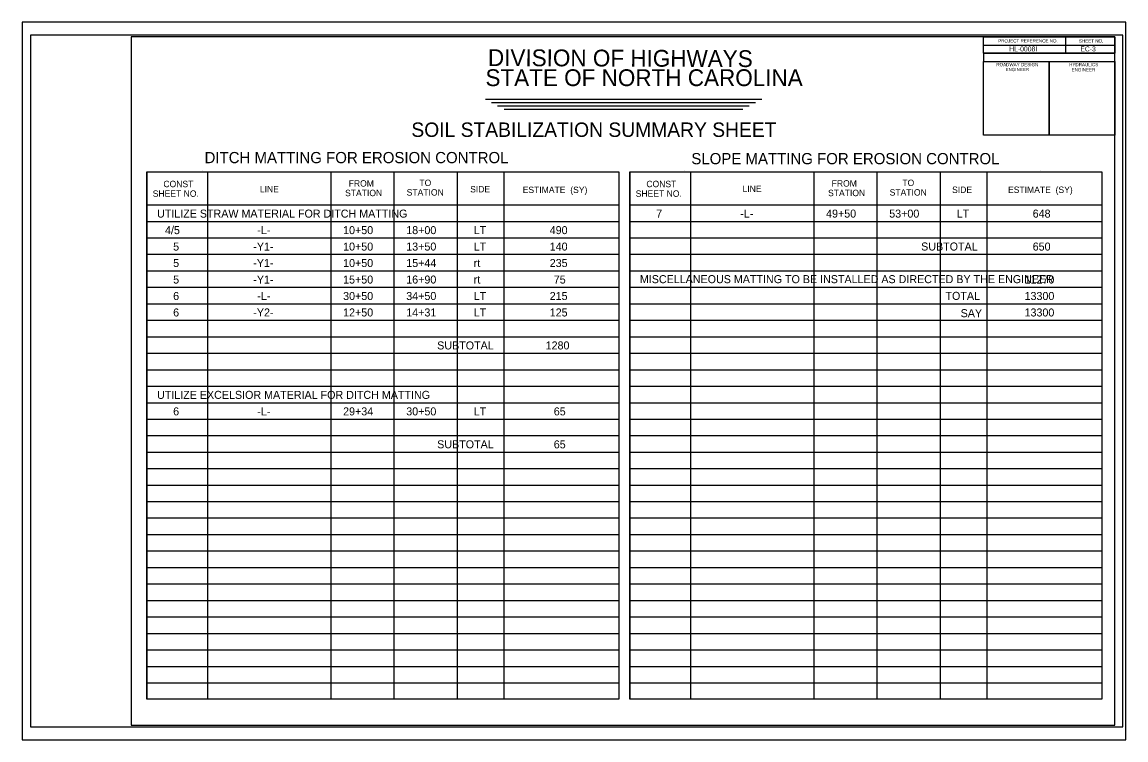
# Model space of a CAD drawing. Extents: x 1206208 to 1207892, y 737235 to 738330.
import ezdxf

# ---------------------------------------------------------------- set-up
doc = ezdxf.new("R2010")
doc.units = 0
for name, color, linetype in [('Matting and PSRM Summary Sheet CELL', 7, 'Continuous'), ('Sheet Plot Border Inside CELL', 7, 'Continuous'), ('Sheet Plot Border Outside CELL', 7, 'Continuous')]:
    doc.layers.add(name, color=color, linetype=linetype)

msp = doc.modelspace()

# ---------------------------------------------------------------- linework, layer by layer
at = {"layer": 'Matting and PSRM Summary Sheet CELL'}
for p, q in [((1207892, 738329.7), (1207892, 738329.7)), ((1206375, 738307.2), (1206375, 738307.2)), ((1207800, 738307.1), (1207800, 738282.1)), ((1207887.5, 738309.7), (1207887.5, 738309.7)), ((1207674.9, 738294.6), (1207875, 738294.6)), ((1207674.9, 738282.1), (1207674.9, 738269.6)), ((1207674.9, 738282.1), (1207875, 738282.1)), ((1207775, 738269.6), (1207775, 738157.2)), ((1206915.4, 738212.3), (1207336.6, 738212.3)), ((1206924.6, 738207.1), (1207326.9, 738207.1)), ((1206933.8, 738201.7), (1207317.3, 738201.7)), ((1206943.5, 738196.8), (1207307.7, 738196.8)), ((1206398.8, 738101), (1206398.8, 737296.6)), ((1206482.9, 738102.5), (1206482.9, 738102.5)), ((1206491.5, 738101), (1206491.5, 737296.6)), ((1206679.4, 738101), (1206679.4, 737296.6)), ((1206775.7, 738101), (1206775.7, 737296.6)), ((1206872, 738101), (1206872, 737296.6)), ((1206943.4, 738101), (1206943.4, 737296.6)), ((1207135.4, 738101), (1207135.4, 737296.6)), ((1207135.4, 738101), (1207855.1, 738101)), ((1207219.5, 738102.5), (1207219.5, 738102.5)), ((1207228.1, 738101), (1207228.1, 737296.6)), ((1207416, 738101), (1207416, 737296.6)), ((1207512.3, 738101), (1207512.3, 737296.6)), ((1207608.6, 738101), (1207608.6, 737296.6)), ((1207680.1, 738101), (1207680.1, 737296.6)), ((1207761, 738102.5), (1207761, 738102.5)), ((1206398.8, 738050.8), (1207118.4, 738050.8)), ((1207135.4, 738050.8), (1207855.1, 738050.8)), ((1206398.8, 738025.6), (1207118.4, 738025.6)), ((1207135.4, 738025.6), (1207855.1, 738025.6)), ((1206398.8, 738000.5), (1207118.4, 738000.5)), ((1207135.4, 738000.5), (1207855.1, 738000.5)), ((1206398.8, 737975.4), (1207118.4, 737975.4)), ((1207135.4, 737975.4), (1207855.1, 737975.4)), ((1206398.8, 737950.2), (1207118.4, 737950.2)), ((1207135.4, 737950.2), (1207855.1, 737950.2)), ((1206398.8, 737925.1), (1207118.4, 737925.1)), ((1207135.4, 737925.1), (1207855.1, 737925.1)), ((1206398.8, 737899.9), (1207118.4, 737899.9)), ((1207135.4, 737899.9), (1207855.1, 737899.9)), ((1206398.8, 737874.8), (1207118.4, 737874.8)), ((1207135.4, 737874.8), (1207855.1, 737874.8)), ((1206398.8, 737849.7), (1207118.4, 737849.7)), ((1207135.4, 737849.7), (1207855.1, 737849.7)), ((1206398.8, 737824.5), (1207118.4, 737824.5)), ((1207135.4, 737824.5), (1207855.1, 737824.5)), ((1206398.8, 737799.4), (1207118.4, 737799.4)), ((1207135.4, 737799.4), (1207855.1, 737799.4)), ((1206398.8, 737774.3), (1207118.4, 737774.3)), ((1207135.4, 737774.3), (1207855.1, 737774.3)), ((1206398.8, 737749.1), (1207118.4, 737749.1)), ((1207135.4, 737749.1), (1207855.1, 737749.1)), ((1206398.8, 737724), (1207118.4, 737724)), ((1207135.4, 737724), (1207855.1, 737724)), ((1206398.8, 737698.8), (1207118.4, 737698.8)), ((1207135.4, 737698.8), (1207855.1, 737698.8)), ((1206398.8, 737673.7), (1207118.4, 737673.7)), ((1207135.4, 737673.7), (1207855.1, 737673.7)), ((1206398.8, 737648.6), (1207118.4, 737648.6)), ((1207135.4, 737648.6), (1207855.1, 737648.6)), ((1206398.8, 737623.4), (1207118.4, 737623.4)), ((1207135.4, 737623.4), (1207855.1, 737623.4)), ((1206398.8, 737598.3), (1207118.4, 737598.3)), ((1207135.4, 737598.3), (1207855.1, 737598.3)), ((1206398.8, 737573.2), (1207118.4, 737573.2)), ((1207135.4, 737573.2), (1207855.1, 737573.2)), ((1206398.8, 737548), (1207118.4, 737548)), ((1207135.4, 737548), (1207855.1, 737548)), ((1206398.8, 737522.9), (1207118.4, 737522.9)), ((1207135.4, 737522.9), (1207855.1, 737522.9)), ((1206398.8, 737497.7), (1207118.4, 737497.7)), ((1207135.4, 737497.7), (1207855.1, 737497.7)), ((1206398.8, 737472.6), (1207118.4, 737472.6)), ((1207135.4, 737472.6), (1207855.1, 737472.6)), ((1206398.8, 737447.5), (1207118.4, 737447.5)), ((1207135.4, 737447.5), (1207855.1, 737447.5)), ((1206398.8, 737422.3), (1207118.4, 737422.3)), ((1207135.4, 737422.3), (1207855.1, 737422.3)), ((1206398.8, 737397.2), (1207118.4, 737397.2)), ((1207135.4, 737397.2), (1207855.1, 737397.2)), ((1206398.8, 737372.1), (1207118.4, 737372.1)), ((1207135.4, 737372.1), (1207855.1, 737372.1)), ((1206398.8, 737346.9), (1207118.4, 737346.9)), ((1207135.4, 737346.9), (1207855.1, 737346.9)), ((1206398.8, 737321.8), (1207118.4, 737321.8)), ((1207135.4, 737321.8), (1207855.1, 737321.8)), ((1206375, 737257.2), (1206375, 737257.2)), ((1206221.5, 737254.7), (1206221.5, 737254.7)), ((1206208.5, 737234.7), (1206208.5, 737234.7))]:
    msp.add_line(p, q, dxfattribs=at)
for points in [[(1207875, 738307.2), (1206375, 738307.2), (1206375, 737257.2), (1207875, 737257.2)], [(1207674.9, 738307.2), (1207875, 738307.2), (1207875, 738282.1), (1207674.9, 738282.1)], [(1207674.9, 738269.6), (1207775, 738269.6), (1207775, 738157.1), (1207674.9, 738157.1)], [(1207775, 738269.6), (1207875, 738269.6), (1207875, 738157.1), (1207775, 738157.1)], [(1206398.8, 738101), (1207118.4, 738101), (1207118.4, 737296.6), (1206398.8, 737296.6)], [(1207135.4, 738101), (1207855.1, 738101), (1207855.1, 737296.6), (1207135.4, 737296.6)]]:
    msp.add_lwpolyline(points, close=True, dxfattribs=at)
at = {"layer": 'Sheet Plot Border Inside CELL'}
msp.add_lwpolyline([(1206221.5, 737254.7), (1207887.5, 737254.7), (1207887.5, 738309.7), (1206221.5, 738309.7)], close=True, dxfattribs=at)
at = {"layer": 'Sheet Plot Border Outside CELL'}
msp.add_lwpolyline([(1206208.5, 737234.7), (1207892, 737234.7), (1207892, 738329.7), (1206208.5, 738329.7)], close=True, dxfattribs=at)

# ---------------------------------------------------------------- texts
at = {"layer": 'Matting and PSRM Summary Sheet CELL'}
for s, height, rotation, p in [('PROJECT REFERENCE NO.', 5, 360, (1207697.1, 738298.5)), ('SHEET NO.', 5, 360, (1207820.3, 738298.4)), ('  DIVISION OF HIGHWAYS', 25.64, 359.7699, (1206899.9, 738262.7)), ('HL-0008I', 7.5, 360, (1207714, 738284.9)), ('EC-3', 7.5, 360, (1207822.5, 738284.9)), ('ROADWAY DESIGN', 5, 360, (1207694.3, 738262.3)), ('HYDRAULICS', 5, 360, (1207805.4, 738262.3)), ('STATE OF NORTH CAROLINA', 25.64, 360, (1206915.2, 738232)), ('ENGINEER', 5, 360, (1207708.3, 738254.8)), ('ENGINEER', 5, 360, (1207809.2, 738254.4)), ('SOIL STABILIZATION SUMMARY SHEET', 21.977, 360, (1206802.2, 738154.5)), ('DITCH MATTING FOR EROSION CONTROL', 17.093, 360, (1206486.8, 738114.4)), ('SLOPE MATTING FOR EROSION CONTROL', 17.093, 360, (1207229.2, 738112.8)), ('CONST', 9.77, 360, (1206424, 738077.8)), ('FROM ', 9.77, 360, (1206706.6, 738078.7)), ('TO', 9.77, 360, (1206814.4, 738079.6)), ('CONST', 9.77, 360, (1207160.6, 738077.8)), ('LINE', 9.76, 360, (1207307.3, 738070.4)), ('FROM ', 9.77, 360, (1207443.2, 738078.7)), ('TO', 9.77, 360, (1207551, 738079.6)), ('SHEET NO.', 9.77, 360, (1206407.7, 738063.1)), ('LINE', 9.76, 360, (1206571.1, 738070)), ('STATION', 9.77, 360, (1206701.1, 738064.1)), ('STATION', 9.77, 360, (1206795, 738065)), ('SIDE', 9.76, 360, (1206891.9, 738069.8)), ('ESTIMATE  (SY)', 9.763, 360, (1206972, 738068.9)), ('SHEET NO.', 9.77, 360, (1207144.3, 738063.1)), ('STATION', 9.77, 360, (1207437.7, 738064.1)), ('STATION', 9.77, 360, (1207531.6, 738065)), ('SIDE', 9.76, 360, (1207626.9, 738069)), ('ESTIMATE  (SY)', 9.763, 360, (1207712.2, 738069)), ('UTILIZE STRAW MATERIAL FOR DITCH MATTING', 12.209, 360, (1206414.3, 738031.4)), ('7', 12.2, 360, (1207175.6, 738031.4)), ('-L-', 12.21, 360, (1207303.9, 738031.4)), ('49+50', 12.21, 360, (1207434.7, 738031.4)), ('53+00', 12.21, 360, (1207531, 738031.4)), ('LT', 12.21, 360, (1207633.9, 738031.4)), ('648', 12.21, 360, (1207749.8, 738031.4)), ('4/5', 12.21, 360, (1206426.5, 738006.2)), ('-L-', 12.21, 360, (1206567.3, 738006.2)), ('10+50', 12.21, 360, (1206698.1, 738006.2)), ('18+00', 12.21, 360, (1206794.4, 738006.2)), ('LT', 12.21, 360, (1206897.3, 738006.2)), ('490', 12.21, 360, (1207013.2, 738006.2)), ('5', 12.2, 360, (1206438.9, 737981.1)), ('-Y1-', 12.21, 360, (1206561.1, 737981.1)), ('10+50', 12.21, 360, (1206698.1, 737981.1)), ('13+50', 12.21, 360, (1206794.4, 737981.1)), ('LT', 12.21, 360, (1206897.3, 737981.1)), ('140', 12.21, 360, (1207013.2, 737981.1)), ('SUBTOTAL', 12.21, 360, (1207579.7, 737981.2)), ('650', 12.21, 360, (1207749.8, 737981.1)), ('5', 12.2, 360, (1206438.9, 737956)), ('-Y1-', 12.21, 360, (1206561.1, 737956)), ('10+50', 12.21, 360, (1206698.1, 737956)), ('15+44', 12.21, 360, (1206794.4, 737956)), ('rt', 12.21, 360, (1206897.3, 737956)), ('235', 12.21, 360, (1207013.2, 737956)), ('5', 12.2, 360, (1206438.9, 737930.8)), ('-Y1-', 12.21, 360, (1206561.1, 737930.8)), ('15+50', 12.21, 360, (1206698.1, 737930.8)), ('16+90', 12.21, 360, (1206794.4, 737930.8)), ('rt', 12.21, 360, (1206897.3, 737930.8)), ('75', 12.21, 360, (1207019.4, 737930.8)), ('MISCELLANEOUS MATTING TO BE INSTALLED AS DIRECTED BY THE ENGINEER', 12.209, 360, (1207150.7, 737931.4)), ('11270', 12.21, 360, (1207737.4, 737930.8)), ('6', 12.2, 360, (1206438.9, 737905.7)), ('-L-', 12.21, 360, (1206567.3, 737905.7)), ('30+50', 12.21, 360, (1206698.1, 737905.7)), ('34+50', 12.21, 360, (1206794.4, 737905.7)), ('LT', 12.21, 360, (1206897.3, 737905.7)), ('215', 12.21, 360, (1207013.2, 737905.7)), ('TOTAL', 12.21, 360, (1207616.8, 737905.9)), ('13300', 12.21, 360, (1207737.4, 737905.7)), ('6', 12.2, 360, (1206438.9, 737880.6)), ('-Y2-', 12.21, 360, (1206561.1, 737880.6)), ('12+50', 12.21, 360, (1206698.1, 737880.6)), ('14+31', 12.21, 360, (1206794.4, 737880.6)), ('LT', 12.21, 360, (1206897.3, 737880.6)), ('125', 12.21, 360, (1207013.2, 737880.6)), ('SAY', 12.21, 360, (1207639.9, 737879.5)), ('13300', 12.21, 360, (1207737.4, 737880.6)), ('SUBTOTAL', 12.21, 360, (1206841.6, 737830.3)), ('1280', 12.21, 360, (1207007, 737830.3)), ('UTILIZE EXCELSIOR MATERIAL FOR DITCH MATTING', 12.209, 360, (1206414.3, 737754.9)), ('6', 12.2, 360, (1206438.9, 737729.7)), ('-L-', 12.21, 360, (1206567.3, 737729.7)), ('29+34', 12.21, 360, (1206698.1, 737729.7)), ('30+50', 12.21, 360, (1206794.4, 737729.7)), ('LT', 12.21, 360, (1206897.3, 737729.7)), ('65', 12.21, 360, (1207019.4, 737729.7)), ('SUBTOTAL', 12.21, 360, (1206841.6, 737679.5)), ('65', 12.21, 360, (1207019.4, 737679.4))]:
    msp.add_text(s, height=height, rotation=rotation, dxfattribs=at).set_placement(p)

doc.saveas('drawing.dxf')
